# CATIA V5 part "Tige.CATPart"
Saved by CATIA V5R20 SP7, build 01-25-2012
Part number: Tige
Bounding box of the stored display mesh (mm): x -3.75 to 3.75, y -24.25 to 24.25, z -3.566 to 3.566
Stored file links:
  F:\Travaux\Modélisations\CFAO_2011\MMS\MMS_GR1\AA_OK\bmadec\Catia\Tige.CATPart
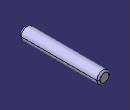
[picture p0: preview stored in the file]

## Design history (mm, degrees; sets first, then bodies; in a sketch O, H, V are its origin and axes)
Body1 (main body)
  Sketch1 on zx-plane, origin (0, 0, 0), H (-1, 0, 0), V (0, 0, 1)
    circle A1 centre (0, 0) radius 3.75
    radius A1 = 3.75
  Pad1: profile Sketch1, direction (0, 1, 0), length 24.25, opposite side length 24.25
  Fillet1: radius 1, on edge [start face of Pad1 | face of Pad1 from Sketch1.A1]
  Fillet2: radius 1, on edge [face of Pad1 from Sketch1.A1 | end face of Pad1]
